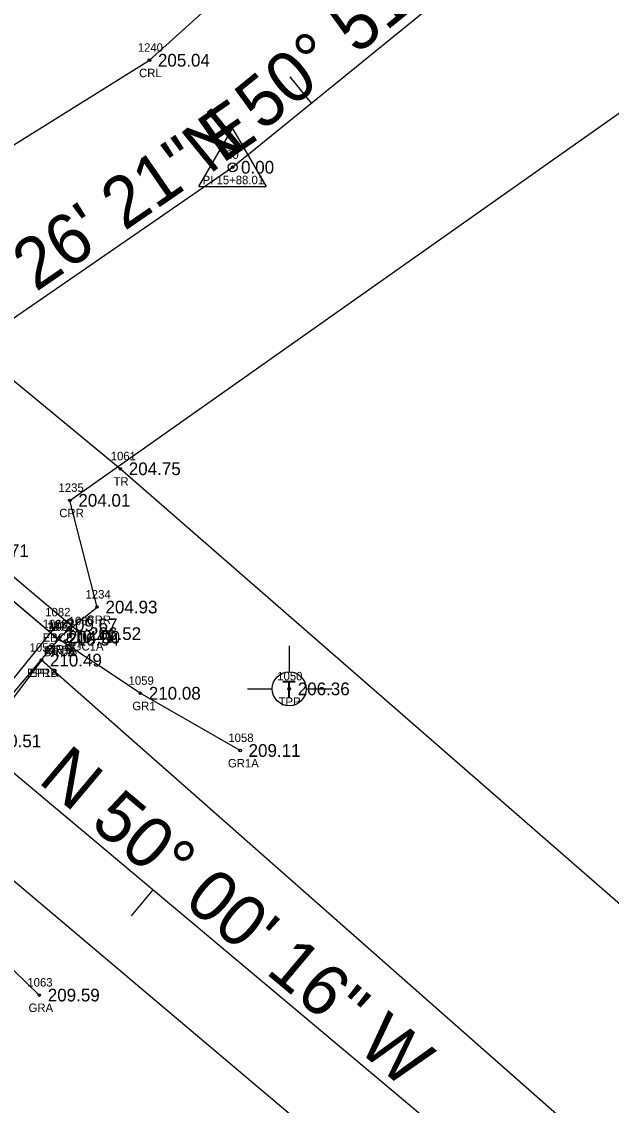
# Model space of a CAD drawing. Extents: x 2259948 to 2261336, y 1064647 to 1065986.
# Drawn here: x 2260830.6 to 2260900.1, y 1065022.5 to 1065150.5 of the extents above; entities that cross this region are included whole.
import ezdxf

# ---------------------------------------------------------------- set-up
doc = ezdxf.new("R2010")
doc.units = 0
for name, color, linetype in [('RD_EX_Bridge', 7, 'Continuous'), ('RD_EX_Bridge_txCode', 7, 'Continuous'), ('RD_EX_GuardRail', 7, 'Continuous'), ('RD_EX_GuardRail_txCode', 7, 'Continuous'), ('RD_EX_H2O', 7, 'Continuous'), ('RD_EX_H2O_txCode', 7, 'Continuous'), ('RD_EX_Road', 7, 'Continuous'), ('RD_EX_Road_txCode', 7, 'Continuous'), ('RD_EX_TX_Bridge_ELEV', 7, 'Continuous'), ('RD_EX_TX_GuardRail_ELEV', 7, 'Continuous'), ('RD_EX_TX_H2O_ELEV', 7, 'Continuous'), ('RD_EX_TX_Road_ELEV', 7, 'Continuous'), ('RD_EX_TX_UT_ELEV', 7, 'Continuous'), ('RD_EX_TX_VEG_ELEV', 7, 'Continuous'), ('RD_EX_UT', 7, 'Continuous'), ('RD_EX_UT_txCode', 7, 'Continuous'), ('RD_EX_VEG', 7, 'Continuous'), ('RD_EX_VEG_txCode', 7, 'Continuous'), ('RD_HC_Cl', 7, 'Continuous'), ('RD_HC_Data', 7, 'Continuous'), ('RD_HC_Data_Tic', 7, 'Continuous'), ('RD_HC_Survey_ELEV', 7, 'Continuous'), ('RD_HC_txCode', 7, 'Continuous'), ('RD_SMD_Locator', 7, 'Continuous')]:
    doc.layers.add(name, color=color, linetype=linetype)

msp = doc.modelspace()

# ---------------------------------------------------------------- linework, layer by layer
at = {"layer": 'RD_EX_Bridge'}
msp.add_line((2260813.68, 1065053.26), (2260834.73, 1065079.24), dxfattribs=at)
msp.add_lwpolyline([(2260834.92, 1065077.53), (2260814.6, 1065053.58), (2260769.11, 1065092.26), (2260789.4, 1065116.14), (2260834.92, 1065077.53)], dxfattribs=at)
at = {"layer": 'RD_EX_GuardRail'}
for points in [[(2260856.34, 1065064.4), (2260844.56, 1065071.16), (2260834.49, 1065077.85), (2260789.73, 1065115.71), (2260781.1, 1065124.5), (2260771.62, 1065134.32)], [(2260832.64, 1065035.52), (2260813.58, 1065053.99), (2260748.98, 1065108.74)]]:
    msp.add_lwpolyline(points, dxfattribs=at)
at = {"layer": 'RD_EX_H2O'}
for points in [[(2260835.04, 1065077.78), (2260839.45, 1065081.34), (2260836.25, 1065093.94), (2260905.11, 1065142.54), (2260939.15, 1065178.33), (2260943.42, 1065185.77), (2260976.49, 1065206.39), (2260992.26, 1065206.09), (2261009.06, 1065194.12), (2261027.03, 1065166.48), (2261074.3, 1065153.35), (2261181.18, 1065157.65), (2261291.85, 1065184.94)], [(2260789.48, 1065116.29), (2260790.36, 1065118.06), (2260803.42, 1065119.58), (2260845.64, 1065145.91), (2260874.83, 1065172.21)]]:
    msp.add_lwpolyline(points, dxfattribs=at)
at = {"layer": 'RD_EX_Road'}
for points in [[(2260832.89, 1065075.07), (2260825.73, 1065065.53), (2260818.6, 1065058.26)], [(2261124.91, 1064827.37), (2261072.16, 1064871.6), (2261053.72, 1064886.47), (2261045.58, 1064893.1), (2260972.89, 1064954.76), (2260940.74, 1064982.39), (2260933.33, 1064988.76), (2260898.06, 1065017.6), (2260832.89, 1065075.07)], [(2261112.68, 1064810.86), (2261032.95, 1064877.72), (2260956.01, 1064942.53), (2260884.53, 1065002.6), (2260818.6, 1065058.26)]]:
    msp.add_lwpolyline(points, dxfattribs=at)
at = {"layer": 'RD_EX_UT'}
for p, q in [((2260837.52, 1065078.2), (2260787.54, 1065120.31)), ((2260862.14, 1065076.75), (2260862.14, 1065073.68)), ((2260857.21, 1065071.69), (2260860.14, 1065071.69)), ((2260864.14, 1065071.69), (2260867.21, 1065071.69))]:
    msp.add_line(p, q, dxfattribs=at)
msp.add_circle((2260862.14, 1065071.68), 2, dxfattribs=at)
at = {"layer": 'RD_EX_VEG'}
msp.add_lwpolyline([(2261134.31, 1064842.95), (2260842.2, 1065097.67), (2260806.91, 1065126.77), (2260758.4, 1065156.57), (2260401.57, 1065481.47), (2260414.95, 1065532.7)], dxfattribs=at)
at = {"layer": 'RD_HC_Cl'}
for p, q in [((2261118.79, 1064819.11), (2260589.55, 1065263.13)), ((2260855.45, 1065133.27), (2260894.66, 1065165.19)), ((2260819.36, 1065108.41), (2260855.45, 1065133.27))]:
    msp.add_line(p, q, dxfattribs=at)
at = {"layer": 'RD_HC_Data'}
for p, q in [((2260851.48, 1065130.98), (2260855.46, 1065137.86)), ((2260855.46, 1065137.86), (2260859.42, 1065130.98)), ((2260851.48, 1065130.98), (2260859.42, 1065130.98))]:
    msp.add_line(p, q, dxfattribs=at)
msp.add_circle((2260855.45, 1065133.27), 0.529, dxfattribs=at)
at = {"layer": 'RD_HC_Data_Tic'}
for p, q in [((2260864.75, 1065140.84), (2260862.23, 1065143.94)), ((2260846.04, 1065047.94), (2260843.47, 1065044.88))]:
    msp.add_line(p, q, dxfattribs=at)
at = {"layer": 'RD_SMD_Locator'}
for centre in [(2260845.64, 1065145.91), (2260855.45, 1065133.27), (2260842.2, 1065097.67), (2260836.25, 1065093.94), (2260839.45, 1065081.34), (2260834.73, 1065079.24), (2260837.52, 1065078.2), (2260834.49, 1065077.85), (2260834.92, 1065077.53), (2260834.92, 1065077.53), (2260835.04, 1065077.78), (2260832.89, 1065075.07), (2260832.89, 1065075.07), (2260862.14, 1065071.68), (2260844.56, 1065071.16), (2260856.34, 1065064.4), (2260832.64, 1065035.52)]:
    msp.add_circle(centre, 0.15, dxfattribs=at)

# ---------------------------------------------------------------- texts
at = {"layer": 'RD_EX_Bridge_txCode'}
for s, p in [('1082', (2260833.34, 1065080.24)), ('1073', (2260833.53, 1065078.53)), ('1051', (2260833.81, 1065078.53)), ('EBCB', (2260833.03, 1065077.24)), ('BRCA', (2260833.18, 1065075.53)), ('BRCB', (2260833.19, 1065075.53))]:
    msp.add_text(s, height=1, dxfattribs=at).set_placement(p)
at = {"layer": 'RD_EX_GuardRail_txCode'}
for s, p in [('1060', (2260833.04, 1065078.85)), ('GR1', (2260833.54, 1065075.85)), ('1059', (2260843.18, 1065072.16)), ('GR1', (2260843.62, 1065069.16)), ('1058', (2260854.95, 1065065.4)), ('GR1A', (2260854.9, 1065062.4)), ('1063', (2260831.23, 1065036.52)), ('GRA', (2260831.37, 1065033.52))]:
    msp.add_text(s, height=1, dxfattribs=at).set_placement(p)
at = {"layer": 'RD_EX_H2O_txCode'}
for s, p in [('1240', (2260844.26, 1065146.91)), ('CRL', (2260844.41, 1065143.91)), ('1235', (2260834.91, 1065094.94)), ('CRR', (2260835, 1065091.94)), ('1234', (2260838.1, 1065082.34)), ('1233', (2260833.69, 1065078.78)), ('CRR', (2260838.2, 1065079.34)), ('CRRA', (2260833.3, 1065075.78))]:
    msp.add_text(s, height=1, dxfattribs=at).set_placement(p)
at = {"layer": 'RD_EX_Road_txCode'}
for s, p in [('1052', (2260831.5, 1065076.07)), ('1053', (2260831.5, 1065076.07)), ('EPRB', (2260831.19, 1065073.07)), ('EP1A', (2260831.48, 1065073.07))]:
    msp.add_text(s, height=1, dxfattribs=at).set_placement(p)
at = {"layer": 'RD_EX_TX_Bridge_ELEV'}
for s, p in [('209.71', (2260825.27, 1065087.24)), ('209.67', (2260835.73, 1065078.49)), ('210.54', (2260835.92, 1065076.78)), ('210.54', (2260835.92, 1065076.78))]:
    msp.add_text(s, height=1.5, dxfattribs=at).set_placement(p)
at = {"layer": 'RD_EX_TX_GuardRail_ELEV'}
for s, p in [('210.47', (2260835.49, 1065077.1)), ('210.08', (2260845.56, 1065070.41)), ('209.11', (2260857.34, 1065063.65)), ('209.59', (2260833.64, 1065034.77))]:
    msp.add_text(s, height=1.5, dxfattribs=at).set_placement(p)
at = {"layer": 'RD_EX_TX_H2O_ELEV'}
for s, p in [('205.04', (2260846.64, 1065145.16)), ('204.01', (2260837.25, 1065093.19)), ('204.93', (2260840.45, 1065080.59)), ('204.90', (2260836.04, 1065077.03))]:
    msp.add_text(s, height=1.5, dxfattribs=at).set_placement(p)
at = {"layer": 'RD_EX_TX_Road_ELEV'}
for s, p in [('210.49', (2260833.89, 1065074.32)), ('210.49', (2260833.89, 1065074.32)), ('210.51', (2260826.73, 1065064.78))]:
    msp.add_text(s, height=1.5, dxfattribs=at).set_placement(p)
at = {"layer": 'RD_EX_TX_UT_ELEV'}
for s, p in [('206.52', (2260838.52, 1065077.45)), ('206.36', (2260863.14, 1065070.93))]:
    msp.add_text(s, height=1.5, dxfattribs=at).set_placement(p)
at = {"layer": 'RD_EX_TX_VEG_ELEV'}
msp.add_text('204.75', height=1.5, dxfattribs=at).set_placement((2260843.2, 1065096.92))
at = {"layer": 'RD_EX_UT'}
msp.add_text('T', height=2, dxfattribs=at).set_placement((2260861.29, 1065070.63))
at = {"layer": 'RD_EX_UT_txCode'}
for s, p in [('1080', (2260836.1, 1065079.2)), ('UGC1A', (2260835.61, 1065076.2)), ('1050', (2260860.72, 1065072.68)), ('TPP', (2260860.88, 1065069.68))]:
    msp.add_text(s, height=1, dxfattribs=at).set_placement(p)
at = {"layer": 'RD_EX_VEG_txCode'}
for s, p in [('1061', (2260841.07, 1065098.67)), ('TR', (2260841.4, 1065095.67))]:
    msp.add_text(s, height=1, dxfattribs=at).set_placement(p)
at = {"layer": 'RD_HC_Data'}
for s, rotation, p in [('N 50%%d 51\' 14" E', 39.146, (2260852.73, 1065132.34)), ('N 55%%d 26\' 21" E', 34.5607, (2260813.8, 1065105.79)), ('N 50%%d 00\' 16" W', 320.0043, (2260832.35, 1065060.73))]:
    msp.add_text(s, height=6, rotation=rotation, dxfattribs=at).set_placement(p)
at = {"layer": 'RD_HC_Survey_ELEV'}
msp.add_text('0.00', height=1.5, dxfattribs=at).set_placement((2260856.45, 1065132.52))
at = {"layer": 'RD_HC_txCode'}
for s, p in [('20', (2260854.68, 1065134.27)), ('PI 15+88.01', (2260851.92, 1065131.27))]:
    msp.add_text(s, height=1, dxfattribs=at).set_placement(p)

doc.saveas('drawing.dxf')
